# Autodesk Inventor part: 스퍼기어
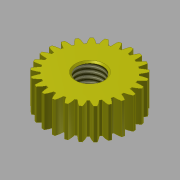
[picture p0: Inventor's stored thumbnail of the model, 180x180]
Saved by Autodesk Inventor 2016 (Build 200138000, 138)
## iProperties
Created: 2017-04
Part Number: 스퍼기어
Material: 강철
Document SubType Name: Modeling
Designer: mduedu
Categories: <?xml version="1.0" encoding="UTF-16"?> <MemberInstance><Categories><FamilyTemplate><FamilyTemplateParameter ValueType="xs:double" Id="1" ObjectReferenceKey="da
Density: 7.85 g/cm^3
Mass: 33.8546 g
Surface Area: 26.941 cm^2
Volume: 4.31269 cm^3
Appearance: 노란색
Author: mduedu
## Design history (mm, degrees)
sketch "Sketch1"
  geometry: C1 r 13.5 at (0, 0)
  constraints: 1 centre point
  dimensions: "d0" = 27 diameter of C1 (= da_da)
extrude "Extrusion1" new body sketch "Sketch1" distance "d1" = 10 (= da_b); taper "d2" = 0 deg
workplane "Work Plane2"
sketch "Sketch2"
  geometry: C1 r 13.5 at (0, 0) reference; C2 r 12.5 at (0, 0)
  constraints: 1 centre point, 1 coincident
  dimensions: "d3" = 25 diameter of C2 (= da_dw)
feature "피치 지름" sketch "Sketch2" dims "d4" = 10, "d5" = 0
workplane "Work Plane8"
workplane "Work Plane9"
feature "스퍼 기어" dims "da_b" = 10, "da_d" = 25, "da_aw" = 25, "da_da" = 27, "da_df" = 22.5, "da_dw" = 25, angle "da_beta" = 0 deg, "da_lefttooth" = 0, "da_righttooth" = 0
sketch "스케치3"
  geometry: C1 r 4.188 at (0, 0); 1 further point
  constraints: 1 centre point, 1 coincident
  dimensions: "d49" = 8.376 diameter of C1
extrude "돌출2" cut sketch "스케치3" stored distance "d50" = 10; taper "d51" = 0 deg
feature "스레드1" dims "d52" = 10, "d53" = 0
chamfer "모따기1" distance "d54" = 0.5; stored, may be unused: second distance "d55" = 2, angle "d56" = 45 deg
body "Solid1"
body "Srf1"
other parameters: "d16" = 25 (= da_aw), "d17" = 0, "d34" = 1.25664 (computed from da_z), "d39" = 0, "d41" = 0, "d43" = 25 (= da_aw), "d46" = 25 (= da_aw), "d47" = 0, "d48" = 0
